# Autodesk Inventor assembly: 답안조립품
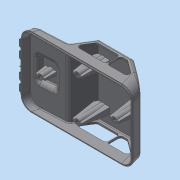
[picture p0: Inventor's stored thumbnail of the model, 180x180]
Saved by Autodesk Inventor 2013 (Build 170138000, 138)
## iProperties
Created: 2015-05
Part Number: 답안조립품
Document SubType Name: Assembly
Designer: Administrator
Author: Administrator
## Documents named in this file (2)
- C:\Users\Administrator\Desktop\450508V1050\답안조립품.iam
- C:\Users\Administrator\Desktop\450508V1050\본체.ipt
